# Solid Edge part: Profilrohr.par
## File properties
Username: bmolnar
Dokumentum tartalom típus: 0
Author: bmolnar
Last saved by: bmolnar
Revision: 95
Sűrűség: 0,000 kg/m^3
Pontosság: 0,990
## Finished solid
Body 1: solid body, 91 faces, 266 edges, 176 vertices.
  Faces by surface: plane 46, cylinder 45
  Edges by curve: line 176, circle 90
Bounding box of the edges (mm): 49.000 x 49.000 x 335.800, from (-24.5, -24.5, -315) to (24.5, 24.5, 20.8).
Cylindrical faces by radius (mm): R0.15 x20, R0.25 x20, R8 x4, R16 x1
Planar faces by outward normal: +x 11, +y 11, +z 1, -x 11, -y 11, -z 1
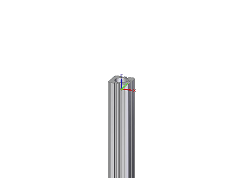
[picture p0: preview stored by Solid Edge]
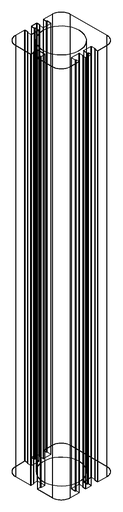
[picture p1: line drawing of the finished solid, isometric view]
